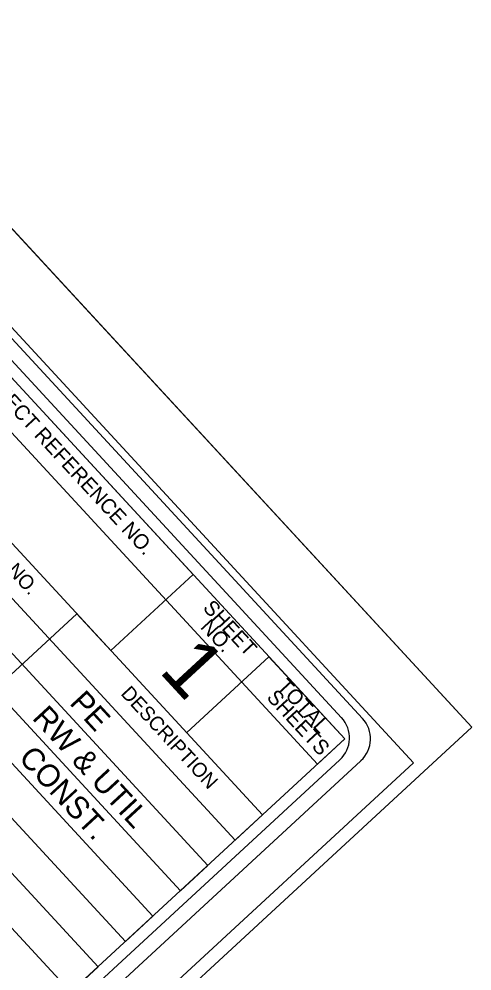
# Model space of a CAD drawing. Extents: x 1695041 to 1706254, y 786537 to 798223.
# Drawn here: x 1705798 to 1706254, y 794266 to 795222 of the extents above; entities that cross this region are included whole.
import ezdxf

# ---------------------------------------------------------------- set-up
doc = ezdxf.new("R2010")
doc.units = 0
for name, color, linetype in [('Sheet Cutting Line CELL', 7, 'Continuous'), ('Sheet Data Field CELL', 7, 'Continuous'), ('Sheet Plot Border Inside CELL', 7, 'Continuous'), ('Sheet Plot Border Outside CELL', 7, 'Continuous'), ('Sheet Title CELL', 7, 'Continuous')]:
    doc.layers.add(name, color=color, linetype=linetype)

msp = doc.modelspace()

# ---------------------------------------------------------------- linework, layer by layer
at = {"layer": 'Sheet Cutting Line CELL'}
msp.add_line((1702826.93, 798222.79), (1706253.58, 794510.54), dxfattribs=at)
at = {"layer": 'Sheet Plot Border Inside CELL'}
msp.add_lwpolyline([(1700478.01, 796001.5), (1703869.05, 792327.83), (1706194.94, 794474.78), (1702803.9, 798148.45)], close=True, dxfattribs=at)
at = {"layer": 'Sheet Plot Border Outside CELL'}
msp.add_lwpolyline([(1706253.58, 794510.54), (1702826.93, 798222.79), (1700402.1, 795984.5), (1703828.75, 792272.26)], close=True, dxfattribs=at)
at = {"layer": 'Sheet Title CELL'}
for points in [[(1706143.56, 794519.16), (1703131.99, 797781.79)], [(1706122.34, 794520.04), (1703232.91, 797650.29)], [(1705538.62, 795079.48), (1706098.2, 794473.26), (1706125.75, 794498.7), (1705566.15, 795104.89)], [(1705455.93, 795003.15), (1706015.51, 794396.93), (1706043.09, 794422.39), (1705483.51, 795028.61)], [(1705642.48, 795022.25), (1705973.14, 794663.98), (1705890.48, 794587.72), (1705856.5, 794624.54), (1705608.5, 794395.62)], [(1705400.82, 794952.28), (1705960.42, 794346.09), (1705987.95, 794371.5), (1705428.37, 794977.71)], [(1705345.73, 794901.43), (1705905.31, 794295.22), (1705932.87, 794320.65), (1705373.29, 794926.87)], [(1705290.6, 794850.54), (1705850.17, 794244.32), (1705877.73, 794269.75), (1705318.18, 794875.94)], [(1705795.09, 794193.47), (1706125.75, 794498.7), (1706049.45, 794581.36), (1705966.81, 794505.03)], [(1703871.31, 792380.95), (1706141.84, 794476.8)], [(1704279.95, 792778.56), (1706120.67, 794477.67)]]:
    msp.add_lwpolyline(points, dxfattribs=at)
for centre in [(1706100.43, 794499.8), (1706121.62, 794498.95)]:
    msp.add_arc(centre, 30, 312.70907, 42.70907, dxfattribs=at)

# ---------------------------------------------------------------- texts
at = {"layer": 'Sheet Data Field CELL'}
for s, p in [('PE        ', (1705848.11, 794534.27)), ('RW & UTIL ', (1705810.64, 794519.19)), ('CONST.    ', (1705796.86, 794478.83))]:
    msp.add_text(s, height=22.5, rotation=312.70907, dxfattribs=at).set_placement(p)
at = {"layer": 'Sheet Title CELL'}
for s, height, p in [('STATE PROJECT REFERENCE NO.', 14.9994, (1705697.81, 794927.98)), ('F. A. PROJ. NO.', 14.4, (1705712.35, 794746.86)), ('SHEET', 14.999, (1705982.25, 794629.78)), ('NO.', 14.999, (1705979.81, 794610.58)), ('1', 58.05, (1705937.83, 794566.72)), ('TOTAL', 14.999, (1706056.71, 794550.71)), ('DESCRIPTION', 14.4, (1705899.73, 794543.8)), ('SHEETS', 14.999, (1706046.38, 794539.8))]:
    msp.add_text(s, height=height, rotation=312.70907, dxfattribs=at).set_placement(p)

doc.saveas('drawing.dxf')
